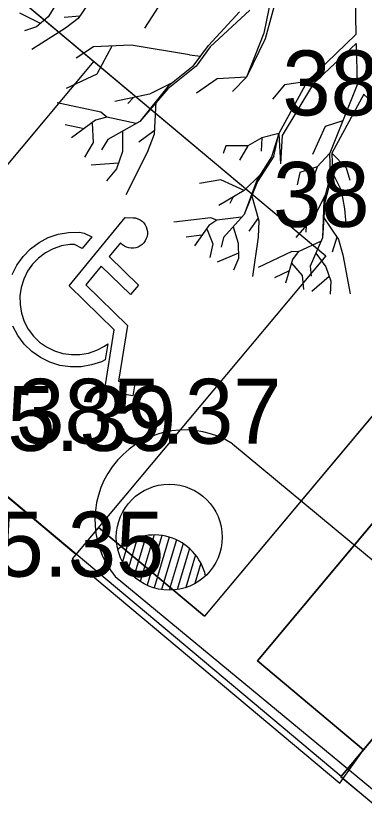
# Model space of a CAD drawing. Extents: x -438233 to -437334, y -1133133 to -1132623.
# Drawn here: x -438098.22 to -438094.2, y -1132977.21 to -1132967.96 of the extents above; entities that cross this region are included whole.
import ezdxf

# ---------------------------------------------------------------- set-up
doc = ezdxf.new("R2010")
doc.units = 0
for name, color, linetype in [('EL3', 7, 'Continuous'), ('Vrstva 1', 7, 'Continuous'), ('Vrstva 10', 7, 'Continuous'), ('Vrstva 15', 7, 'Continuous'), ('Vrstva 3', 7, 'Continuous'), ('Vrstva 50', 7, 'Continuous'), ('Vrstva 53', 7, 'Continuous')]:
    doc.layers.add(name, color=color, linetype=linetype)

# ---------------------------------------------------------------- blocks, each defined once
blk = doc.blocks.new('ELJL31_2_1')
at = {"layer": 'EL3'}
for p, q in [((10.50516, 25), (24.4949, 25)), ((6.27724, 20), (28.72281, 20)), ((3.37727, 15), (31.62278, 15)), ((1.45902, 10), (33.54102, 10)), ((0, 0), (35, 0)), ((0.35902, 5), (34.64102, 5)), ((0.35902, -5), (34.64102, -5)), ((1.45902, -10), (33.54102, -10)), ((3.37727, -15), (31.62278, -15)), ((6.27724, -20), (28.72281, -20)), ((10.50516, -25), (24.4949, -25))]:
    blk.add_line(p, q, dxfattribs=at)
blk.add_circle((0, 0), 35, dxfattribs=at)
blk.add_arc((35, 0), 34.99996, 119.999947, 239.999954, dxfattribs=at)

msp = doc.modelspace()

# ---------------------------------------------------------------- linework, layer by layer
at = {"layer": 'Vrstva 1'}
for p, q in [((-438105.1829, -1132961.9029), (-438094.6429, -1132970.733)), ((-438110.4187, -1132963.3789), (-438094.4626, -1132976.7464)), ((-438094.3102, -1132967.4202), (-438094.2933, -1132968.1766)), ((-438095.2513, -1132967.6428), (-438095.3569, -1132968.1597)), ((-438095.1634, -1132967.5605), (-438095.3424, -1132968.2258)), ((-438097.3269, -1132967.7307), (-438097.5052, -1132967.9911)), ((-438097.7479, -1132967.8073), (-438097.8527, -1132967.9734)), ((-438096.5351, -1132967.7863), (-438096.7391, -1132968.1048)), ((-438096.0004, -1132968.3024), (-438095.64, -1132967.9129)), ((-438095.9778, -1132968.3193), (-438095.5206, -1132967.8935)), ((-438097.9406, -1132968.0492), (-438098.1785, -1132967.9282)), ((-438097.8527, -1132967.9734), (-438097.9874, -1132968.0879)), ((-438097.4866, -1132967.9645), (-438097.6689, -1132967.979)), ((-438097.5052, -1132967.9911), (-438097.6527, -1132968.1048)), ((-438097.9874, -1132968.0879), (-438098.1269, -1132968.1347)), ((-438097.6527, -1132968.1048), (-438098.0406, -1132968.3484)), ((-438095.3569, -1132968.1597), (-438095.5601, -1132968.6701)), ((-438094.2933, -1132968.1766), (-438094.8594, -1132968.7177)), ((-438095.3424, -1132968.2258), (-438095.5601, -1132968.6701)), ((-438094.2917, -1132968.2814), (-438094.7836, -1132968.7427)), ((-438094.2917, -1132968.2814), (-438094.2796, -1132968.758)), ((-438097.3278, -1132968.3193), (-438097.5269, -1132968.4484)), ((-438096.8915, -1132968.3008), (-438097.3278, -1132968.3193)), ((-438097.1157, -1132968.3105), (-438097.289, -1132968.633)), ((-438096.2165, -1132968.4121), (-438096.8915, -1132968.3008)), ((-438096.1746, -1132968.5427), (-438096.0004, -1132968.3024)), ((-438095.9778, -1132968.3193), (-438096.1407, -1132968.5435)), ((-438096.2165, -1132968.4121), (-438096.0899, -1132968.4266)), ((-438097.3259, -1132968.4853), (-438100.2157, -1132971.9348)), ((-438096.1407, -1132968.5435), (-438096.4673, -1132968.8056)), ((-438096.1746, -1132968.5427), (-438096.4641, -1132968.7749)), ((-438097.289, -1132968.633), (-438097.6463, -1132968.7999)), ((-438096.4101, -1132968.7314), (-438096.6826, -1132968.8645)), ((-438095.898, -1132968.6895), (-438096.1367, -1132968.8556)), ((-438095.5601, -1132968.6701), (-438095.898, -1132968.6895)), ((-438095.5601, -1132968.6701), (-438095.7198, -1132968.8362)), ((-438095.119, -1132968.7572), (-438095.2593, -1132968.9241)), ((-438094.8594, -1132968.7177), (-438095.1835, -1132969.3209)), ((-438094.7836, -1132968.7427), (-438095.1472, -1132969.3443)), ((-438094.8594, -1132968.7177), (-438095.119, -1132968.7572)), ((-438096.4641, -1132968.7749), (-438096.7907, -1132969.1806)), ((-438096.4673, -1132968.8056), (-438096.7907, -1132969.1806)), ((-438094.2796, -1132968.758), (-438094.5941, -1132969.5467)), ((-438096.6826, -1132968.8645), (-438097.0826, -1132968.9507)), ((-438096.8657, -1132968.9032), (-438096.9302, -1132968.9733)), ((-438094.2021, -1132968.8645), (-438094.5707, -1132969.5459)), ((-438094.203, -1132968.8677), (-438093.7143, -1132969.3128)), ((-438097.2439, -1132969.0741), (-438097.7487, -1132968.9677)), ((-438096.6076, -1132968.9515), (-438096.6286, -1132969.3289)), ((-438097.1753, -1132969.1306), (-438097.2439, -1132969.0741)), ((-438097.3036, -1132969.1669), (-438097.581, -1132969.3709)), ((-438097.3455, -1132969.2007), (-438097.3318, -1132969.4233)), ((-438097.1753, -1132969.1306), (-438097.3036, -1132969.1669)), ((-438096.8359, -1132969.2048), (-438097.1753, -1132969.1306)), ((-438096.7907, -1132969.1806), (-438097.1641, -1132969.3886)), ((-438094.4457, -1132969.1733), (-438094.6497, -1132969.2394)), ((-438097.4382, -1132969.2652), (-438097.656, -1132969.2217)), ((-438096.9915, -1132969.2918), (-438096.9947, -1132969.5281)), ((-438096.6254, -1132969.291), (-438096.8036, -1132969.4193)), ((-438094.6497, -1132969.2394), (-438094.7949, -1132969.5612)), ((-438097.1641, -1132969.3886), (-438097.2366, -1132969.508)), ((-438096.6286, -1132969.3289), (-438096.7076, -1132969.5386)), ((-438095.3835, -1132969.3717), (-438095.5432, -1132969.4612)), ((-438095.3835, -1132969.3717), (-438095.3892, -1132969.5257)), ((-438095.1835, -1132969.3209), (-438095.3835, -1132969.3717)), ((-438095.1835, -1132969.3209), (-438095.2698, -1132969.5894)), ((-438095.2424, -1132969.5813), (-438095.1835, -1132969.3209)), ((-438095.1835, -1132969.3209), (-438095.165, -1132969.6692)), ((-438095.1472, -1132969.3443), (-438095.165, -1132969.6692)), ((-438097.3318, -1132969.4233), (-438097.4334, -1132969.5926)), ((-438095.7964, -1132969.462), (-438095.8295, -1132969.5515)), ((-438095.5432, -1132969.4612), (-438095.7964, -1132969.462)), ((-438095.5432, -1132969.4612), (-438095.6383, -1132969.6281)), ((-438096.9947, -1132969.5281), (-438097.0608, -1132969.7297)), ((-438096.7076, -1132969.5386), (-438096.9552, -1132970.0297)), ((-438095.2424, -1132969.5813), (-438095.4303, -1132969.8741)), ((-438094.5941, -1132969.5467), (-438094.7416, -1132969.7039)), ((-438094.5892, -1132969.7934), (-438094.5941, -1132969.5467)), ((-438094.5707, -1132969.5459), (-438094.4046, -1132969.7152)), ((-438094.5707, -1132969.5459), (-438094.5658, -1132969.7765)), ((-438097.0383, -1132969.6612), (-438097.3568, -1132969.6846)), ((-438095.2698, -1132969.5894), (-438095.4367, -1132969.8499)), ((-438097.0608, -1132969.7297), (-438097.1762, -1132969.8652)), ((-438094.9408, -1132969.7717), (-438094.9731, -1132969.912)), ((-438094.7416, -1132969.7039), (-438094.9408, -1132969.7717)), ((-438094.7416, -1132969.7039), (-438094.8086, -1132969.895)), ((-438094.4046, -1132969.7152), (-438094.3658, -1132969.8596)), ((-438095.8577, -1132969.8555), (-438096.1044, -1132969.8991)), ((-438095.5851, -1132969.9789), (-438095.8577, -1132969.8555)), ((-438095.4367, -1132969.8499), (-438095.5859, -1132970.2579)), ((-438095.4053, -1132969.7999), (-438095.5851, -1132969.9789)), ((-438094.5892, -1132969.7934), (-438094.6658, -1132970.0926)), ((-438094.5658, -1132969.7765), (-438094.6521, -1132970.1144)), ((-438094.5658, -1132969.7765), (-438094.465, -1132969.9765)), ((-438095.4303, -1132969.8741), (-438095.5859, -1132970.2579)), ((-438095.5851, -1132969.9789), (-438095.8778, -1132970.1531)), ((-438095.5021, -1132970.0281), (-438095.4182, -1132970.3305)), ((-438094.6513, -1132970.037), (-438094.7658, -1132970.2628)), ((-438094.465, -1132969.9765), (-438094.4247, -1132970.191)), ((-438095.719, -1132970.0579), (-438095.7512, -1132970.1305)), ((-438094.6658, -1132970.0926), (-438094.6795, -1132970.5273)), ((-438094.6521, -1132970.1144), (-438094.6795, -1132970.5273)), ((-438094.4247, -1132970.191), (-438094.4078, -1132970.4047)), ((-438095.9722, -1132970.2934), (-438096.3988, -1132970.345)), ((-438095.9028, -1132970.32), (-438095.9948, -1132970.3821)), ((-438095.9028, -1132970.32), (-438095.9722, -1132970.2934)), ((-438095.615, -1132970.2886), (-438095.9028, -1132970.32)), ((-438095.5859, -1132970.2579), (-438095.8254, -1132970.5208)), ((-438095.4263, -1132970.3007), (-438095.5327, -1132970.449)), ((-438094.7658, -1132970.2628), (-438094.9892, -1132970.52)), ((-438094.6715, -1132970.2829), (-438094.4965, -1132970.5442)), ((-438095.9948, -1132970.3821), (-438096.1585, -1132970.6184)), ((-438096.019, -1132970.4208), (-438095.948, -1132970.5934)), ((-438095.7141, -1132970.3982), (-438095.6545, -1132970.5861)), ((-438095.4182, -1132970.3305), (-438095.4247, -1132970.5176)), ((-438094.8674, -1132970.3805), (-438094.8747, -1132970.4595)), ((-438096.0746, -1132970.4966), (-438096.2585, -1132970.5192)), ((-438095.948, -1132970.5934), (-438095.9835, -1132970.7538)), ((-438095.8254, -1132970.5208), (-438095.8504, -1132970.6345)), ((-438095.6545, -1132970.5861), (-438095.6529, -1132970.7627)), ((-438095.4247, -1132970.5176), (-438095.4892, -1132970.9716)), ((-438094.6965, -1132970.566), (-438094.9602, -1132970.6869)), ((-438094.6795, -1132970.5273), (-438094.8231, -1132970.853)), ((-438094.5142, -1132970.5176), (-438094.5674, -1132970.6926)), ((-438094.4965, -1132970.5442), (-438094.4441, -1132970.7224)), ((-438095.0335, -1132970.6837), (-438095.4238, -1132970.8676)), ((-438094.9602, -1132970.6869), (-438095.0335, -1132970.6837)), ((-438094.9602, -1132970.6869), (-438095.0271, -1132970.7748)), ((-438094.6429, -1132970.733), (-438097.5328, -1132974.1824)), ((-438095.6529, -1132970.7022), (-438095.8988, -1132970.8071)), ((-438095.6529, -1132970.7627), (-438095.7085, -1132970.8998)), ((-438095.0271, -1132970.7748), (-438095.1085, -1132971.0498)), ((-438094.7561, -1132970.7022), (-438094.64, -1132970.8603)), ((-438094.4441, -1132970.7224), (-438094.3618, -1132971.174)), ((-438095.0376, -1132970.8184), (-438094.9166, -1132970.9611)), ((-438094.8231, -1132970.853), (-438094.811, -1132970.9692)), ((-438094.64, -1132970.8603), (-438094.5836, -1132971.0272)), ((-438095.0666, -1132970.9087), (-438095.2343, -1132970.9885)), ((-438094.9166, -1132970.9611), (-438094.8997, -1132971.1232)), ((-438094.6029, -1132970.9708), (-438094.8021, -1132971.1466)), ((-438094.5836, -1132971.0272), (-438094.5916, -1132971.1756)), ((-438095.722, -1132972.904), (-438095.722, -1132972.904)), ((-438096.941, -1132972.987), (-438096.941, -1132972.987)), ((-438091.5768, -1132973.3017), (-438094.4666, -1132976.7512)), ((-438097.077, -1132974.44), (-438097.077, -1132974.44)), ((-438094.4666, -1132976.7512), (-438069.1706, -1132997.9434))]:
    msp.add_line(p, q, dxfattribs=at)
for points in [[(-438097.089, -1132971.5873), (-438097.6087, -1132971.0813), (-438096.9609, -1132970.2905), (-438096.8687, -1132970.2936), (-438096.8439, -1132970.2958), (-438096.8159, -1132970.3047), (-438096.7898, -1132970.3167), (-438096.7673, -1132970.3337), (-438096.7478, -1132970.3526), (-438096.7302, -1132970.3747), (-438096.7194, -1132970.3987), (-438096.7097, -1132970.4264), (-438096.7044, -1132970.4535), (-438096.7053, -1132970.4808), (-438096.7093, -1132970.5087), (-438096.7176, -1132970.5348), (-438096.7302, -1132970.5603), (-438096.746, -1132970.5828), (-438096.7655, -1132970.6029), (-438096.7876, -1132970.6193), (-438096.8122, -1132970.632), (-438096.8387, -1132970.6416), (-438096.8658, -1132970.6457), (-438096.8918, -1132970.646), (-438096.9203, -1132970.6427), (-438096.9483, -1132970.6338), (-438096.9713, -1132970.6223), (-438096.9938, -1132970.6053), (-438097.0133, -1132970.5864), (-438097.0177, -1132970.5821), (-438097.1473, -1132970.7416), (-438096.8094, -1132971.0706), (-438096.8995, -1132971.1807), (-438097.2381, -1132970.8511), (-438097.4177, -1132971.0695), (-438096.9356, -1132971.5389), (-438097.0408, -1132972.1813), (-438096.8511, -1132972.211), (-438096.8746, -1132972.3505), (-438097.2026, -1132972.2974), (-438097.089, -1132971.5873)], [(-438098.2683, -1132970.9505), (-438098.2134, -1132970.8427), (-438098.143, -1132970.7403), (-438098.0588, -1132970.6538), (-438097.9583, -1132970.5806), (-438097.8514, -1132970.5223), (-438097.7362, -1132970.4842), (-438097.6171, -1132970.4622), (-438097.4921, -1132970.4606), (-438097.4381, -1132970.4704), (-438097.3485, -1132970.5137), (-438097.4593, -1132970.6476), (-438097.549, -1132970.6018), (-438097.601, -1132970.6037), (-438097.6991, -1132970.6193), (-438097.7946, -1132970.6509), (-438097.8843, -1132970.6978), (-438097.9658, -1132970.7602), (-438098.0329, -1132970.8292), (-438098.0925, -1132970.9116), (-438098.1358, -1132971.0013), (-438098.1655, -1132971.0982), (-438098.179, -1132971.1974), (-438098.1783, -1132971.2958), (-438098.1621, -1132971.3971), (-438098.1287, -1132971.4907), (-438098.0823, -1132971.5798), (-438098.0224, -1132971.66), (-438097.951, -1132971.7296), (-438097.8704, -1132971.7861), (-438097.7788, -1132971.8313), (-438097.6844, -1132971.8622), (-438097.5839, -1132971.8744), (-438097.4856, -1132971.8725), (-438097.3862, -1132971.8569), (-438097.2901, -1132971.8247), (-438097.2028, -1132971.7778), (-438097.1636, -1132971.7488), (-438097.1952, -1132971.9342), (-438097.2351, -1132971.9564)], [(-438097.2351, -1132971.9564), (-438097.3528, -1132971.9945), (-438097.4725, -1132972.0159), (-438097.595, -1132972.0175), (-438097.7159, -1132971.9987), (-438097.8334, -1132971.9638), (-438097.9417, -1132971.9096), (-438098.0429, -1132971.8379), (-438098.1295, -1132971.7537), (-438098.2038, -1132971.6544), (-438098.2609, -1132971.5475)]]:
    msp.add_lwpolyline(points, dxfattribs=at)
at = {"layer": 'Vrstva 10'}
for points in [[(-438095.722, -1132972.904), (-438079.649, -1132986.224)], [(-438097.077, -1132974.44), (-438080.864, -1132987.825)]]:
    msp.add_lwpolyline(points, dxfattribs=at)
msp.add_arc((-438096.2745, -1132973.7822), 1.0376, 57.82496, 219.34005, dxfattribs=at)
at = {"layer": 'Vrstva 15'}
for p, q in [((-438093.4165, -1132971.7605), (-438096.0455, -1132974.8985)), ((-438092.8032, -1132972.2742), (-438095.4322, -1132975.4123)), ((-438097.2719, -1132973.871), (-438096.0455, -1132974.8985)), ((-438095.4322, -1132975.4123), (-438094.2057, -1132976.4398))]:
    msp.add_line(p, q, dxfattribs=at)
msp.add_lwpolyline([(-438093.4165, -1132971.7605), (-438096.0455, -1132974.8985), (-438097.2719, -1132973.871), (-438097.5766, -1132974.2347), (-438094.4815, -1132976.8276), (-438094.2057, -1132976.4398), (-438095.4322, -1132975.4123), (-438092.8032, -1132972.2742)], close=True, dxfattribs=at)
at = {"layer": 'Vrstva 50'}
for points in [[(-438105.1829, -1132961.9029), (-438094.6429, -1132970.733), (-438097.5328, -1132974.1824), (-438108.0728, -1132965.3523)], [(-438091.5768, -1132973.3017), (-438066.2733, -1132994.5002), (-438069.1631, -1132997.9497), (-438094.4666, -1132976.7512)]]:
    msp.add_lwpolyline(points, close=True, dxfattribs=at)

# ---------------------------------------------------------------- block references
at = {"layer": 'Vrstva 53', "xscale": 0.0175, "yscale": 0.0175, "rotation": -106.66592339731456}
msp.add_blockref('ELJL31_2_1', (-438096.4519, -1132973.9842), dxfattribs=at)

# ---------------------------------------------------------------- texts
at = {"layer": 'Vrstva 3'}
for s, p in [('385.43 ', (-438095.144, -1132969.111)), ('385.41 ', (-438095.252, -1132970.399)), ('385.37 ', (-438098.222, -1132972.904)), ('385.39 ', (-438099.441, -1132972.987)), ('385.35 ', (-438099.577, -1132974.44))]:
    msp.add_text(s, height=0.75, dxfattribs=at).set_placement(p)

doc.saveas('drawing.dxf')
